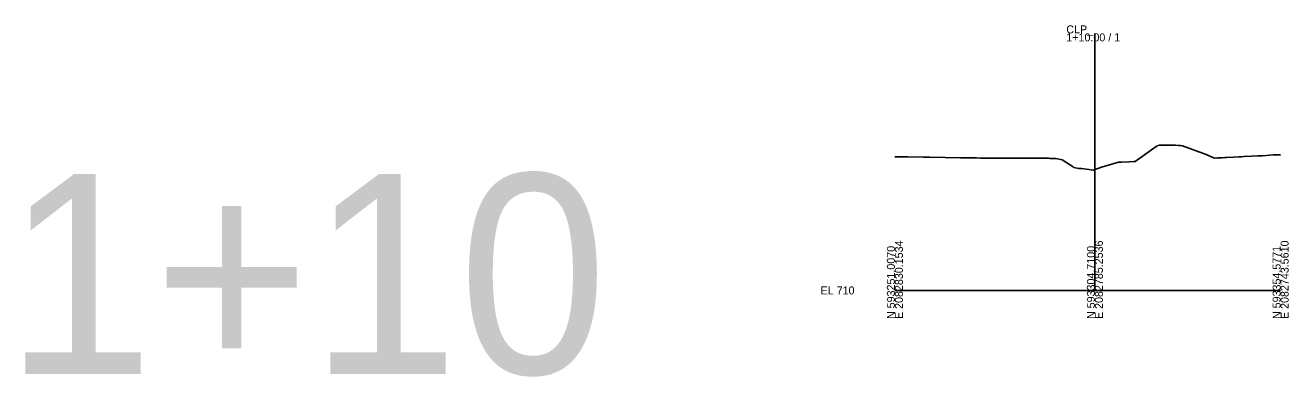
# Model space of a CAD drawing. Extents: x -577 to 1138, y -35 to 4556.
# Drawn here: x 695.6 to 1137.8, y 969.8 to 1092.8 of the extents above; entities that cross this region are included whole.
import ezdxf

# ---------------------------------------------------------------- set-up
doc = ezdxf.new("R2010")
doc.units = 0
for name, color, linetype in [('GK_Cells', 7, 'Continuous'), ('SC_Scratch1', 7, 'Continuous'), ('XS_X_Ground_Line', 7, 'Continuous')]:
    doc.layers.add(name, color=color, linetype=linetype)

msp = doc.modelspace()

# ---------------------------------------------------------------- linework, layer by layer
at = {"layer": 'GK_Cells'}
for p, q in [((1070, 1000), (1070, 1090)), ((1000, 1000), (1070, 1000)), ((1070, 1000), (1135, 1000))]:
    msp.add_line(p, q, dxfattribs=at)
at = {"layer": 'XS_X_Ground_Line'}
for p, q in [((1084.06, 1045.18), (1091.47, 1050.45)), ((1091.47, 1050.45), (1091.81, 1050.58)), ((1091.81, 1050.58), (1092.64, 1050.88)), ((1092.64, 1050.88), (1092.75, 1050.92)), ((1092.75, 1050.92), (1098.16, 1050.91)), ((1098.16, 1050.91), (1099.21, 1050.78)), ((1099.21, 1050.78), (1099.94, 1050.69)), ((1099.94, 1050.69), (1100.66, 1050.6)), ((1100.66, 1050.6), (1108.91, 1047.65)), ((1000, 1046.82), (1002.17, 1046.78)), ((1002.17, 1046.78), (1003.09, 1046.77)), ((1003.09, 1046.77), (1004.48, 1046.74)), ((1004.48, 1046.74), (1009.97, 1046.65)), ((1009.97, 1046.65), (1011.71, 1046.62)), ((1011.71, 1046.62), (1012.26, 1046.62)), ((1012.26, 1046.62), (1022.92, 1046.47)), ((1022.92, 1046.47), (1023.1, 1046.47)), ((1023.1, 1046.47), (1025.15, 1046.43)), ((1025.15, 1046.43), (1026.87, 1046.4)), ((1026.87, 1046.4), (1028.56, 1046.38)), ((1028.56, 1046.38), (1029.85, 1046.37)), ((1029.85, 1046.37), (1034.73, 1046.35)), ((1034.73, 1046.35), (1038.18, 1046.33)), ((1038.18, 1046.33), (1038.43, 1046.33)), ((1038.43, 1046.33), (1038.96, 1046.33)), ((1038.96, 1046.33), (1048.59, 1046.28)), ((1048.59, 1046.28), (1051.31, 1046.27)), ((1051.31, 1046.27), (1051.81, 1046.27)), ((1051.81, 1046.27), (1052.43, 1046.33)), ((1052.43, 1046.33), (1052.64, 1046.28)), ((1052.64, 1046.28), (1053.73, 1046.3)), ((1053.73, 1046.3), (1054.21, 1046.21)), ((1054.21, 1046.21), (1054.55, 1046.2)), ((1054.55, 1046.2), (1056.29, 1046.16)), ((1056.29, 1046.16), (1058.6, 1045.77)), ((1058.6, 1045.77), (1062.43, 1043.27)), ((1072.26, 1043.17), (1078.24, 1044.94)), ((1078.24, 1044.94), (1079.26, 1044.87)), ((1079.26, 1044.87), (1081.94, 1045.04)), ((1081.94, 1045.04), (1083.59, 1045.15)), ((1083.59, 1045.15), (1084.06, 1045.18)), ((1108.91, 1047.65), (1111.26, 1046.6)), ((1111.26, 1046.6), (1111.86, 1046.35)), ((1111.86, 1046.35), (1111.93, 1046.35)), ((1111.93, 1046.35), (1112.5, 1046.38)), ((1112.5, 1046.38), (1112.86, 1046.37)), ((1112.86, 1046.37), (1113.3, 1046.39)), ((1113.3, 1046.39), (1113.31, 1046.39)), ((1113.31, 1046.39), (1113.31, 1046.39)), ((1113.31, 1046.39), (1113.32, 1046.39)), ((1113.32, 1046.39), (1113.32, 1046.39)), ((1113.32, 1046.39), (1113.32, 1046.39)), ((1113.32, 1046.39), (1113.36, 1046.39)), ((1113.36, 1046.39), (1113.36, 1046.39)), ((1113.36, 1046.39), (1113.39, 1046.39)), ((1113.39, 1046.39), (1113.41, 1046.39)), ((1113.41, 1046.39), (1113.41, 1046.39)), ((1113.41, 1046.39), (1113.43, 1046.39)), ((1113.43, 1046.39), (1113.48, 1046.4)), ((1113.48, 1046.4), (1113.52, 1046.4)), ((1113.52, 1046.4), (1113.52, 1046.4)), ((1113.52, 1046.4), (1113.53, 1046.4)), ((1113.53, 1046.4), (1113.68, 1046.41)), ((1113.68, 1046.41), (1113.74, 1046.41)), ((1113.74, 1046.41), (1114, 1046.43)), ((1114, 1046.43), (1114.51, 1046.45)), ((1114.51, 1046.45), (1115.51, 1046.51)), ((1115.51, 1046.51), (1116.02, 1046.54)), ((1116.02, 1046.54), (1118.58, 1046.68)), ((1118.58, 1046.68), (1120.42, 1046.78)), ((1120.42, 1046.78), (1121.17, 1046.82)), ((1121.17, 1046.82), (1122.09, 1046.85)), ((1122.09, 1046.85), (1124.82, 1046.98)), ((1124.82, 1046.98), (1127.04, 1047.08)), ((1127.04, 1047.08), (1128.62, 1047.16)), ((1128.62, 1047.16), (1132.37, 1047.45)), ((1132.37, 1047.45), (1135, 1047.51)), ((1062.43, 1043.27), (1062.62, 1043.01)), ((1062.62, 1043.01), (1064.35, 1042.71)), ((1064.35, 1042.71), (1064.37, 1042.71)), ((1064.37, 1042.71), (1064.41, 1042.7)), ((1064.41, 1042.7), (1064.55, 1042.68)), ((1064.55, 1042.68), (1065.33, 1042.68)), ((1065.33, 1042.68), (1067.89, 1042.32)), ((1067.89, 1042.32), (1069.41, 1042.1)), ((1069.41, 1042.1), (1069.42, 1042.1)), ((1069.42, 1042.1), (1071.4, 1042.84)), ((1071.4, 1042.84), (1072.26, 1043.17))]:
    msp.add_line(p, q, dxfattribs=at)

# ---------------------------------------------------------------- texts
at = {"layer": 'GK_Cells'}
for s, p in [('CLP_', (1060, 1090)), ('1+10.00 / 1', (1060, 1087.2)), ('EL 710', (974, 998.6))]:
    msp.add_text(s, height=2.8, dxfattribs=at).set_placement(p)
for s, p in [('E 2082830.1534', (1002.8, 990)), ('E 2082785.2536', (1072.8, 990)), ('E 2082743.5610', (1137.8, 990)), ('N 593251.0070', (1000, 990)), ('N 593304.7100', (1070, 990)), ('N 593354.5771', (1135, 990))]:
    msp.add_text(s, height=2.8, rotation=90, dxfattribs=at).set_placement(p)
at = {"layer": 'SC_Scratch1'}
msp.add_text('1+10', height=70, dxfattribs=at).set_placement((688.5, 970.79))

doc.saveas('drawing.dxf')
